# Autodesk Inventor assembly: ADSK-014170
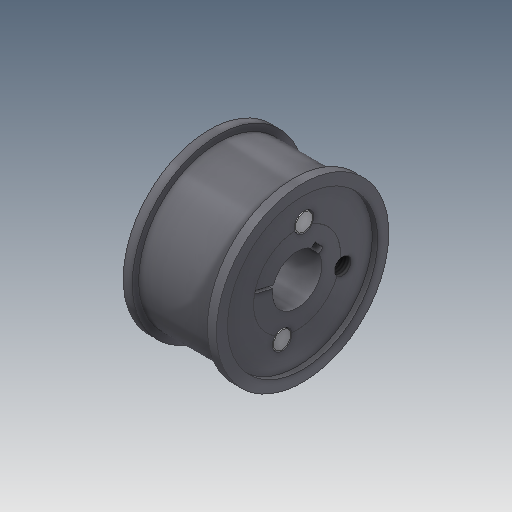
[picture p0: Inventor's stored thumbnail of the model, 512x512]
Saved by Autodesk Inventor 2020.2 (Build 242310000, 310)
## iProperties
Created: 2019-10
Part Number: ADSK-014170
Document SubType Name: Assembly
Designer: lutzd
Mass: 1076.47 g
Surface Area: 430.647 cm^2
Volume: 137.177 cm^3
Density: 7.84734 g/cm^3
VLDS_Profile: Default Assembly
VLDS_TimeStamp: 2016-07-29
VLDS_FailCnt: 0
VLDS_AcceptCnt: 0
Dimensions: 122,2x122,2x47,2 mm
Mass: 1,076 kg
DocNumber: ADSK-014170
Folder: 01 - Themengebiete\Simplification\01 - Packaging machine\
VDS_Category: 3D Komponenten
VDS_NumSchm: Autodesk
Title: wheel
Author: lutzd
Revision Number: -
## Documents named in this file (5)
- D:\07 - DEMODATEN\OTX 2019 - Dataset - UPDATE - Dez2019\Designs\07-Packing machine\ADSK-014170.iam
- D:\07 - DEMODATEN\OTX 2019 - Dataset - UPDATE - Dez2019\Designs\07-Packing machine\Parts\ADSK-011717.ipt
- D:\07 - DEMODATEN\OTX 2019 - Dataset - UPDATE - Dez2019\Designs\07-Packing machine\Parts\ADSK-011754.ipt
- D:\07 - DEMODATEN\OTX 2019 - Dataset - UPDATE - Dez2019\Content Center Files\de-DE\ISO 2338(2)\ISO 2338 - 10 m6 x 24.ipt
- D:\07 - DEMODATEN\OTX 2019 - Dataset - UPDATE - Dez2019\Content Center Files\de-DE\ISO 4029\ISO 4029 - M10 x 20 - ISO.ipt
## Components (5 placed, 4 different names)
1. ADSK-011717:1
2. ADSK-011754:1
3. ISO 2338 10 m6 x 24:1
4. ISO 2338 10 m6 x 24:2
5. ISO 4029 M10 x 20:1
